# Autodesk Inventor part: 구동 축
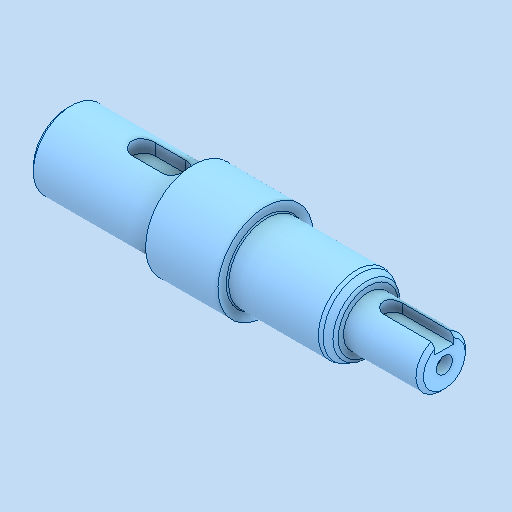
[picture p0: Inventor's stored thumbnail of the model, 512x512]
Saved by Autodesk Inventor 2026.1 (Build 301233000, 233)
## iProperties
Created: 2025-09
Part Number: 구동 축
Material: 강철, 탄소
Document SubType Name: Modeling
Designer: PC-30
Density: 7.85 g/cm^3
Appearance: 기본값
Author: jhkim
Sending System: Autodesk Inventor 2026
Preprocessor: ST-DEVELOPER v20.1
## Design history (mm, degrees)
feature "솔리드1"
node "솔리드2"
